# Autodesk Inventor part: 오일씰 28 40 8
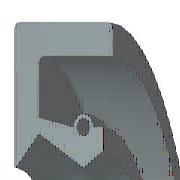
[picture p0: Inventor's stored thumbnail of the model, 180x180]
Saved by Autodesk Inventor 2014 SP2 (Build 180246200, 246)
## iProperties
IsCustomPart: 1
Created: 2012-02
Part Number: 오일씰 28 40 8
Material: 고무
Description: Oil-seal
Document SubType Name: Modeling
Standard: KS B 2804
Designer: mduedu
Standards Organization: KS
Language: en-US
Size Designation: D - 28 40 8
Categories: <MemberInstance><Categories><Category DisplayName="Shaft Parts" InternalName="7f7aeb1f-a693-4053-b835-cee3144e0d98" Mnemonic="SHFT"><Category DisplayName="Seali
Density: 0.93 g/cm^3
Mass: 2.83894 g
Surface Area: 40.7521 cm^2
Volume: 3.05262 cm^3
Appearance: 고무 - 검은색 - 버전 1.1
Author: mduedu
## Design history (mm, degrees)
sketch "Sketch1"
  geometry: L1 (0, 20)-(8, 20); L2 (8, 18.25)-(1.75, 18.25); L3 (1.75, 15.75)-(4.9, 14); L4 (4.9, 14)-(0, 14); L5 (0, 0)-(9.586, 0) reference; L6 (4.9, 14)-(6.3, 14.875); L7 (0, 18)-(0, -3) reference; L8 (-1.941, 0)-(11.507, 0) reference; L9 (4.2, 16.1)-(1.75, 16.71); L10 (1.75, 16.71)-(1.75, 18.25); L11 (0, 20)-(0, 14.088); L12 (4.9, 14)-(0, 14); L13 (1.75, 15.75)-(0.152, 14.028); L14 (8, 20)-(8, 18.25); L15 (5.6, 16.1)-(6.3, 16.1); L16 (6.3, 16.1)-(6.3, 14.875); C1 r 0.455 at (4.9, 16.1); A1 r 0.7 centre (4.9, 16.1) between (5.6, 16.1) and (4.2, 16.1); A2 r 0.088 centre (0.087, 14.088) between (0, 14.088) and (0.152, 14.028); 1 further point
  constraints: 28 end point, 5 horizontal alignment, 5 point on line, 4 point on circle, 4 vertical alignment, 3 centre point, 3 tangent, 2 collinear, 2 horizontal, 2 perpendicular, 1 coincident, 1 parallel
  dimensions: "d0" = 40 diameter of L1 L5 (= SD2); "d1" = 1.75 distance of L1.end L2.start (= SD); "d2" = 0.91 diameter of C1 (= SPDI); "d3" = 1.4 diameter of A1 (= SPDA); "d4" = 28 diameter of L3.end L5 (= NND); "d5" = 31.5 diameter of L3.start L5 (= TKDM); "d7" = 33.42 diameter of L9.end L5 (= TKDM + 0.24 x SWDT); "d8" = 1.75 distance between parallel lines of L11 L10 (= SD); "d9" = 4.9 distance from line of L11 C1.centre (= SPDST); "d10" = 32.2 diameter of C1.centre L5 (= HLDM); "d11" = 0.0875 radius of A2 (= 0.25 x LAB); "d12" = 6.3 distance between parallel lines of L11 L16 (= SDI); "d13" = 29.75 diameter of L6.end L5 (= ABDM); "d14" = 8 distance from line of L11 L1.end (= SWDT)
revolve "Body" stored, may be unused: angle "d17" = 90 deg
revolve "Spring1" stored, may be unused: angle "d18" = 90 deg
fillet "Fillet1" dims "d6" = 0.4 (= RR)
body "Solid1"
other parameters: "SD2" = 40 [user parameter; used in 1 equation term], "SWDT" = 8 [user parameter; used in 2 equation terms], "RR" = 0.4 [user parameter; used in 1 equation term], "SD" = 1.75 [user parameter; used in 2 equation terms], "NND" = 28 [user parameter; used in 1 equation term], "SPDA" = 1.4 [user parameter; used in 1 equation term], "SPDI" = 0.91 [user parameter; used in 1 equation term], "TKDM" = 31.5 [user parameter; used in 2 equation terms], "HLDM" = 32.2 [user parameter; used in 1 equation term], "ABDM" = 29.75 [user parameter; used in 1 equation term], "SDI" = 6.3 [user parameter; used in 1 equation term], "SPDST" = 4.9 [user parameter; used in 1 equation term], "LAB" = 0.35 [user parameter; used in 1 equation term], "d15" = 0, "d16" = 0, "d19" = 0
